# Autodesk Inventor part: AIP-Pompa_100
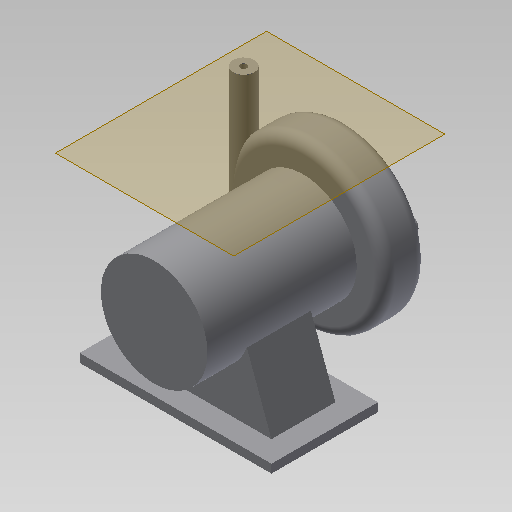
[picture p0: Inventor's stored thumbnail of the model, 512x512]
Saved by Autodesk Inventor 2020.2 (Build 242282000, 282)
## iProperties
Created: 2014-06
Part Number: AIP-Pompa_100
Material: Ogólny
Document SubType Name: Modeling
Designer: F.Stasiak
Density: 1 g/cm^3
Appearance: Domyślna
Catalog Web Link: www.expertbooks.pl
Manager: www.cadconsulting.pl
Company: Fabian Stasiak CAD Consulting
Author: F.Stasiak
Subject: Zbiór ćwiczeń. Autodesk Inventor 2020. Kurs Professional
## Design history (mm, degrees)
sketch "Szkic1"
  geometry: C1 r 125 at (0, 0); 1 further point
  constraints: 1 centre point, 1 coincident
  dimensions: "d0" = 250 diameter of C1
extrude "Wyciągnięcie proste1" new body sketch "Szkic1" stored distance "d1" = 350; taper "d2" = 0 deg
sketch "Szkic2"
  geometry: C1 r 125 at (0, 0) reference; C2 r 190 at (0, 0)
  constraints: 1 centre point, 1 coincident
  dimensions: "d3" = 380 diameter of C2
extrude "Wyciągnięcie proste2" join sketch "Szkic2" distance "d4" = 100; taper "d5" = 0 deg
fillet "Zaokrąglenie1" dims "d6" = 25
node "Płaszczyzna konstrukcyjna1"
sketch "Szkic3"
  geometry: L1 (-165, -175)-(165, -175) reference; C1 r 25 at (165, -200); 6 further points; 1 other entity
  constraints: 1 centre point, 1 coincident, 3 other
extrude "Wyciągnięcie proste3" join sketch "Szkic3" distance "d8" = 250; taper "d9" = 0 deg
sketch "Szkic4"
  geometry: C1 r 20 at (-100, 0); 2 further points
  constraints: 1 centre point, 1 horizontal alignment
  dimensions: "d10" = 40 diameter of C1; "d11" = 100 distance of point (0, 0) C1.centre
extrude "Wyciągnięcie proste4" join sketch "Szkic4" distance "d12" = 50; taper "d13" = 0 deg
sketch "Szkic5"
  geometry: L1 (101.55, 0)-(175, -200); L2 (175, -200)-(-175, -200); L3 (-175, -200)-(-101.55, 0); L4 (-101.55, 0)-(101.55, 0); 3 further points
  constraints: 8 end point, 2 midpoint, 1 coincident, 1 horizontal, 1 parallel, 1 vertical alignment
  dimensions: "d14" = 350 distance of L1.end L2.end; "d15" = 200 distance between parallel lines of L4 L2
extrude "Wyciągnięcie proste5" join sketch "Szkic5" stored distance "d16" = 150; taper "d17" = 0 deg
sketch "Szkic6"
  geometry: L1 (350, 0)-(350, -150) reference; L2 (0, 0)-(350, 0) reference; L3 (0, 0)-(0, -150) reference; L4 (350, -150)-(0, -150) reference; L5 (-50, -200)-(-50, 50); L6 (-50, 50)-(400, 50); L7 (400, 50)-(400, -200); L8 (400, -200)-(-50, -200); 1 further point
  constraints: 8 end point, 3 other
  dimensions: "d18" = 450 distance of L5.end L6.end
extrude "Wyciągnięcie proste6" join sketch "Szkic6" distance "d19" = 20; taper "d20" = 0 deg
hole "Otwór1" diameter "d23" = 21.971; stored, may be unused: countersink angle "d27" = 90 deg, drill point angle "d29" = 118 deg; dims "d21" = 10, "d22" = 10, "d24" = 6, "d25" = 4, "d26" = 2, "d28" = 13
hole "Otwór2" diameter "d32" = 16; stored, may be unused: countersink angle "d36" = 90 deg, drill point angle "d38" = 118 deg; dims "d33" = 6, "d34" = 4, "d35" = 2, "d37" = 15, "d39" = 10, "d40" = 10
node "Bryła1"
